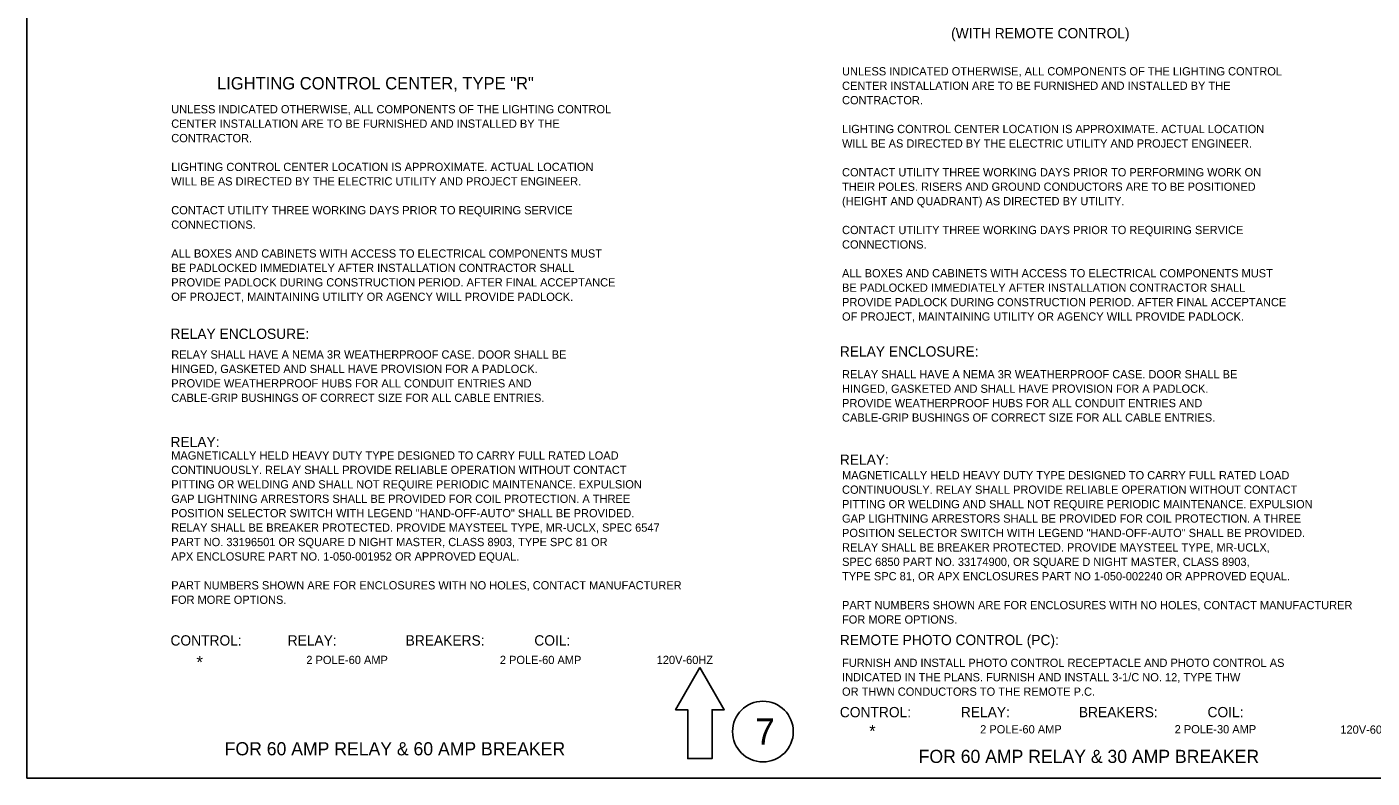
# Model space of a CAD drawing. Extents: x 100006 to 118406, y 96592 to 102182.
# Drawn here: x 110206 to 112163, y 99886 to 100980 of the extents above; entities that cross this region are included whole.
import ezdxf

# ---------------------------------------------------------------- set-up
doc = ezdxf.new("R2010")
doc.units = 0
for name, color, linetype in [('Default', 7, 'Continuous'), ('Level 7', 7, 'Continuous'), ('Level 9', 7, 'Continuous')]:
    doc.layers.add(name, color=color, linetype=linetype)

msp = doc.modelspace()

# ---------------------------------------------------------------- linework, layer by layer
at = {"layer": 'Default'}
msp.add_lwpolyline([(110206.1, 102085.7), (113405.8, 102085.7), (113405.8, 99886.1), (110206.1, 99886.1)], close=True, dxfattribs=at)
at = {"layer": 'Level 9'}
msp.add_lwpolyline([(111185.4, 100046.9), (111149.9, 99985.5), (111167.6, 99985.5), (111167.6, 99914.5), (111203.1, 99914.5), (111203.1, 99985.5), (111220.8, 99985.5)], close=True, dxfattribs=at)
msp.add_circle((111277.1, 99953.8), 44.2, dxfattribs=at)

# ---------------------------------------------------------------- texts
at = {"layer": 'Level 7'}
for s, height, p in [('(WITH REMOTE CONTROL)', 15, (111550.9, 100962.9)), ('LIGHTING CONTROL CENTER, TYPE "R"', 18, (110482.7, 100888.5)), ('UNLESS INDICATED OTHERWISE, ALL COMPONENTS OF THE LIGHTING CONTROL', 12, (111392.2, 100908.9)), ('CENTER INSTALLATION ARE TO BE FURNISHED AND INSTALLED BY THE', 12, (111392.2, 100887.9)), ('UNLESS INDICATED OTHERWISE, ALL COMPONENTS OF THE LIGHTING CONTROL', 12, (110416.1, 100853.7)), ('CONTRACTOR.', 12, (111392.2, 100866.9)), ('CENTER INSTALLATION ARE TO BE FURNISHED AND INSTALLED BY THE', 12, (110416.1, 100832.7)), ('LIGHTING CONTROL CENTER LOCATION IS APPROXIMATE. ACTUAL LOCATION', 12, (111392.2, 100824.9)), ('CONTRACTOR.', 12, (110416.1, 100811.7)), ('WILL BE AS DIRECTED BY THE ELECTRIC UTILITY AND PROJECT ENGINEER.', 12, (111392.2, 100803.9)), ('LIGHTING CONTROL CENTER LOCATION IS APPROXIMATE. ACTUAL LOCATION', 12, (110416.1, 100769.7)), ('CONTACT UTILITY THREE WORKING DAYS PRIOR TO PERFORMING WORK ON', 12, (111392.2, 100761.9)), ('WILL BE AS DIRECTED BY THE ELECTRIC UTILITY AND PROJECT ENGINEER.', 12, (110416.1, 100748.7)), ('THEIR POLES. RISERS AND GROUND CONDUCTORS ARE TO BE POSITIONED', 12, (111392.2, 100740.9)), ('(HEIGHT AND QUADRANT) AS DIRECTED BY UTILITY.', 12, (111392.2, 100719.9)), ('CONTACT UTILITY THREE WORKING DAYS PRIOR TO REQUIRING SERVICE', 12, (110416.1, 100706.7)), ('CONNECTIONS.', 12, (110416.1, 100685.7)), ('CONTACT UTILITY THREE WORKING DAYS PRIOR TO REQUIRING SERVICE', 12, (111392.2, 100677.9)), ('ALL BOXES AND CABINETS WITH ACCESS TO ELECTRICAL COMPONENTS MUST', 12, (110416.1, 100643.7)), ('CONNECTIONS.', 12, (111392.2, 100656.9)), ('BE PADLOCKED IMMEDIATELY AFTER INSTALLATION CONTRACTOR SHALL', 12, (110416.1, 100622.7)), ('PROVIDE PADLOCK DURING CONSTRUCTION PERIOD. AFTER FINAL ACCEPTANCE', 12, (110416.1, 100601.7)), ('ALL BOXES AND CABINETS WITH ACCESS TO ELECTRICAL COMPONENTS MUST', 12, (111392.2, 100614.9)), ('OF PROJECT, MAINTAINING UTILITY OR AGENCY WILL PROVIDE PADLOCK.', 12, (110416.1, 100580.7)), ('BE PADLOCKED IMMEDIATELY AFTER INSTALLATION CONTRACTOR SHALL', 12, (111392.2, 100593.9)), ('PROVIDE PADLOCK DURING CONSTRUCTION PERIOD. AFTER FINAL ACCEPTANCE', 12, (111392.2, 100572.9)), ('OF PROJECT, MAINTAINING UTILITY OR AGENCY WILL PROVIDE PADLOCK.', 12, (111392.2, 100551.9)), ('RELAY ENCLOSURE:', 15, (110415, 100525.3)), ('RELAY ENCLOSURE:', 15, (111389, 100499.6)), ('RELAY SHALL HAVE A NEMA 3R WEATHERPROOF CASE. DOOR SHALL BE', 12, (110416.1, 100496.7)), ('HINGED, GASKETED AND SHALL HAVE PROVISION FOR A PADLOCK.', 12, (110416.1, 100475.7)), ('RELAY SHALL HAVE A NEMA 3R WEATHERPROOF CASE. DOOR SHALL BE', 12, (111392.2, 100467.9)), ('PROVIDE WEATHERPROOF HUBS FOR ALL CONDUIT ENTRIES AND', 12, (110416.1, 100454.7)), ('HINGED, GASKETED AND SHALL HAVE PROVISION FOR A PADLOCK.', 12, (111392.2, 100446.9)), ('CABLE-GRIP BUSHINGS OF CORRECT SIZE FOR ALL CABLE ENTRIES.', 12, (110416.1, 100433.7)), ('PROVIDE WEATHERPROOF HUBS FOR ALL CONDUIT ENTRIES AND', 12, (111392.2, 100425.9)), ('CABLE-GRIP BUSHINGS OF CORRECT SIZE FOR ALL CABLE ENTRIES.', 12, (111392.2, 100404.9)), ('RELAY:', 15, (110415, 100367.8)), ('MAGNETICALLY HELD HEAVY DUTY TYPE DESIGNED TO CARRY FULL RATED LOAD ', 12, (110416.1, 100349.7)), ('RELAY:', 15, (111389, 100342.1)), ('CONTINUOUSLY. RELAY SHALL PROVIDE RELIABLE OPERATION WITHOUT CONTACT ', 12, (110416.1, 100328.7)), ('PITTING OR WELDING AND SHALL NOT REQUIRE PERIODIC MAINTENANCE. EXPULSION ', 12, (110416.1, 100307.7)), ('MAGNETICALLY HELD HEAVY DUTY TYPE DESIGNED TO CARRY FULL RATED LOAD ', 12, (111392.2, 100320.9)), ('GAP LIGHTNING ARRESTORS SHALL BE PROVIDED FOR COIL PROTECTION. A THREE ', 12, (110416.1, 100286.7)), ('CONTINUOUSLY. RELAY SHALL PROVIDE RELIABLE OPERATION WITHOUT CONTACT ', 12, (111392.2, 100299.9)), ('PITTING OR WELDING AND SHALL NOT REQUIRE PERIODIC MAINTENANCE. EXPULSION ', 12, (111392.2, 100278.9)), ('POSITION SELECTOR SWITCH WITH LEGEND "HAND-OFF-AUTO" SHALL BE PROVIDED.  ', 12, (110416.1, 100265.7)), ('GAP LIGHTNING ARRESTORS SHALL BE PROVIDED FOR COIL PROTECTION. A THREE ', 12, (111392.2, 100257.9)), ('RELAY SHALL BE BREAKER PROTECTED. PROVIDE MAYSTEEL TYPE, MR-UCLX, SPEC 6547 ', 12, (110416.1, 100244.7)), ('POSITION SELECTOR SWITCH WITH LEGEND "HAND-OFF-AUTO" SHALL BE PROVIDED.  ', 12, (111392.2, 100236.9)), ('PART NO. 33196501 OR SQUARE D NIGHT MASTER, CLASS 8903, TYPE SPC 81 OR', 12, (110416.1, 100223.7)), ('RELAY SHALL BE BREAKER PROTECTED. PROVIDE MAYSTEEL TYPE, MR-UCLX,', 12, (111392.2, 100215.9)), ('APX ENCLOSURE PART NO. 1-050-001952 OR APPROVED EQUAL.', 12, (110416.1, 100202.7)), ('SPEC 6850 PART NO. 33174900, OR SQUARE D NIGHT MASTER, CLASS 8903,', 12, (111392.2, 100194.9)), ('TYPE SPC 81, OR APX ENCLOSURES PART NO 1-050-002240 OR APPROVED EQUAL.', 12, (111392.2, 100173.9)), ('PART NUMBERS SHOWN ARE FOR ENCLOSURES WITH NO HOLES, CONTACT MANUFACTURER', 12, (110416.1, 100160.7)), ('FOR MORE OPTIONS.  ', 12, (110416.1, 100139.7)), ('PART NUMBERS SHOWN ARE FOR ENCLOSURES WITH NO HOLES, CONTACT MANUFACTURER', 12, (111392.2, 100131.9)), ('FOR MORE OPTIONS.', 12, (111392.2, 100110.9)), ('CONTROL:            RELAY:                  BREAKERS:             COIL:', 15, (110415, 100079)), ('REMOTE PHOTO CONTROL (PC):', 15, (111389, 100079.6)), ('*', 18, (110452.8, 100045.8)), ('2 POLE-60 AMP', 12, (110612.7, 100052.1)), ('2 POLE-60 AMP', 12, (110894.3, 100052.1)), ('120V-60HZ', 12, (111122.5, 100052.1)), ('FURNISH AND INSTALL PHOTO CONTROL RECEPTACLE AND PHOTO CONTROL AS', 12, (111392.2, 100047.9)), ('INDICATED IN THE PLANS. FURNISH AND INSTALL 3-1/C NO. 12, TYPE THW ', 12, (111392.2, 100026.9)), ('OR THWN CONDUCTORS TO THE REMOTE P.C. ', 12, (111392.2, 100005.9)), ('CONTROL:             RELAY:                  BREAKERS:             COIL:', 15, (111389, 99974.6)), ('*', 18, (111431.7, 99945.6)), ('2 POLE-60 AMP', 12, (111593.2, 99951.1)), ('2 POLE-30 AMP', 12, (111876.2, 99951.2)), ('120V-60HZ', 12, (112117.3, 99950.7))]:
    msp.add_text(s, height=height, dxfattribs=at).set_placement(p)
at = {"layer": 'Level 9'}
for s, height, p in [('7', 38.3, (111265.9, 99934.7)), ('FOR 60 AMP RELAY & 60 AMP BREAKER', 19.156, (110493.9, 99919.2)), ('FOR 60 AMP RELAY & 30 AMP BREAKER', 19.156, (111503.7, 99908.1))]:
    msp.add_text(s, height=height, dxfattribs=at).set_placement(p)

doc.saveas('drawing.dxf')
